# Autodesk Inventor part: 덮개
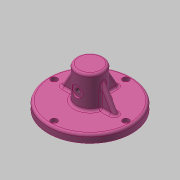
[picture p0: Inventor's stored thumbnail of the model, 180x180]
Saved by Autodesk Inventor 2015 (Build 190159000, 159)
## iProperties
Created: 2017-08
Part Number: 덮개
Material: 알루미늄 6061
Document SubType Name: Modeling
Designer: mduedu
Density: 2.71 g/cm^3
Mass: 336.252 g
Surface Area: 314.319 cm^2
Volume: 124.078 cm^3
Appearance: 분홍색
Author: mduedu
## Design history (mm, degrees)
sketch "스케치1"
  geometry: C1 r 52.5 at (0, 0); 1 further point
  constraints: 1 centre point, 1 coincident
  dimensions: "d55" = 105 diameter of C1
extrude "돌출1" new body sketch "스케치1" distance "d5" = 10; taper "d6" = 0 deg
sketch "스케치2"
  geometry: C1 r 17 at (0, 0); 1 further point
  constraints: 1 centre point, 1 coincident
  dimensions: "d74" = 34 diameter of C1
extrude "돌출2" join sketch "스케치2" distance "d9" = 40; taper "d10" = 0 deg
sketch "스케치3"
  geometry: C1 r 37 at (0, 0); 1 further point
  constraints: 1 centre point, 1 coincident
  dimensions: "d56" = 74 diameter of C1
extrude "돌출3" join sketch "스케치3" distance "d12" = 8; taper "d13" = 0 deg
sketch "스케치4"
  geometry: C1 r 33 at (0, 0); 1 further point
  constraints: 1 centre point, 1 coincident
  dimensions: "d57" = 66 diameter of C1
extrude "돌출4" cut sketch "스케치4" distance "d16" = 7; taper "d17" = 0 deg
sketch "스케치5"
  geometry: C1 r 9 at (0, 0); 1 further point
  constraints: 1 centre point, 1 coincident
  dimensions: "d18" = 18 diameter of C1
extrude "돌출5" cut sketch "스케치5" distance "d19" = 47; taper "d20" = 0 deg
node "작업 평면1"
sketch "스케치11"
  geometry: L1 (-52.5, -10)-(52.5, -10) reference; 2 further points
  constraints: 1 vertical alignment
  dimensions: "d78" = 28 distance from line of point (0, 18) L1
hole "구멍5" sketch "스케치11" at (0, 18) diameter "d79" = 5.917; stored, may be unused: countersink angle "d83" = 90 deg, drill point angle "d85" = 118 deg; dims "d80" = 6, "d81" = 14, "d82" = 2, "d84" = 8
fillet "모깎기9" dims "d86" = 3
fillet "모깎기5" dims "d40" = 1
sketch "스케치12"
  geometry: C1 r 2.5 at (0, 0); 1 further point
  constraints: 1 centre point, 1 coincident
  dimensions: "d87" = 5 diameter of C1
extrude "돌출6" join sketch "스케치12" distance "d88" = 3; taper "d89" = 0 deg
fillet "모깎기10" dims "d91" = 1
chamfer "모따기1" distance "d41" = 1; stored, may be unused: second distance "d42" = 2, angle "d43" = 45 deg
fillet "모깎기7" dims "d45" = 3
fillet "모깎기8" dims "d46" = 3
sketch "스케치10" dims "d59" = 90
  geometry: 3 further points
  constraints: 2 vertical alignment, 1 coincident, 2 other
hole "구멍4" sketch "스케치10" at (0, 45) diameter "d60" = 4.5; stored, may be unused: countersink angle "d64" = 90 deg, drill point angle "d66" = 118 deg; dims "d61" = 6, "d62" = 8, "d63" = 4.6, "d65" = 8
sketch "스케치13"
  geometry: L1 (52.5, 7)-(52.5, 0) reference; L2 (52.5, 0)-(47.25, 0) reference; L3 (47.25, 0)-(47.25, 5.4) reference; L4 (47.25, 5.4)-(49, 5.4) reference; L5 (49, 5.4)-(49, 10) reference; L6 (49, 10)-(49.5, 10) reference; L7 (-49.5, 10)-(-49, 10) reference; L8 (-49, 10)-(-49, 5.4) reference; L9 (-49, 5.4)-(-47.25, 5.4) reference; L10 (-47.25, 5.4)-(-47.25, 0) reference; L11 (-47.25, 0)-(-52.5, 0) reference; L12 (-52.5, 0)-(-52.5, 7) reference; L13 (-3.5, 46)-(-8, 46) reference; L14 (-9, 45)-(-9, -1) reference; L15 (-9, -1)-(-30, -1) reference; L16 (-33, -4)-(-33, -8) reference; L17 (-33, -8)-(-36, -8) reference; L18 (-36, -8)-(-37, -7) reference; L19 (-37, -7)-(-37, 0) reference; L20 (-37, 0)-(-42.75, 0) reference; L21 (-42.75, 0)-(-42.75, 5.4) reference; L22 (-42.75, 5.4)-(-41, 5.4) reference; L23 (-41, 5.4)-(-41, 10) reference; L24 (-41, 10)-(-20, 10) reference; L25 (-17, 13)-(-17, 47) reference; L26 (-14, 50)-(14, 50) reference; L27 (17, 47)-(17, 13) reference; L28 (20, 10)-(41, 10) reference; L29 (41, 10)-(41, 5.4) reference; L30 (41, 5.4)-(42.75, 5.4) reference; L31 (42.75, 5.4)-(42.75, 0) reference; L32 (42.75, 0)-(37, 0) reference; L33 (37, 0)-(37, -7) reference; L34 (37, -7)-(36, -8) reference; L35 (36, -8)-(33, -8) reference; L36 (33, -8)-(33, -4) reference; L37 (30, -1)-(9, -1) reference; L38 (9, -1)-(9, 45) reference; L39 (8, 46)-(3.5, 46) reference; L40 (2.5, 45)-(2.5, 43) reference; L41 (2.5, 43)-(-2.5, 43) reference; L42 (-2.5, 43)-(-2.5, 45) reference; L43 (17, 40)-(34.321, 10); L44 (-49.5, 10)-(49.5, 10) reference; A1 r 3 centre (49.5, 7) between (52.5, 7) and (49.5, 10) reference; A2 r 3 centre (-49.5, 7) between (-49.5, 10) and (-52.5, 7) reference; A3 r 1 centre (-3.5, 45) between (-2.5, 45) and (-3.5, 46) reference; A4 r 1 centre (-8, 45) between (-8, 46) and (-9, 45) reference; A5 r 3 centre (-30, -4) between (-30, -1) and (-33, -4) reference; A6 r 3 centre (-20, 13) between (-20, 10) and (-17, 13) reference; A7 r 3 centre (-14, 47) between (-14, 50) and (-17, 47) reference; A8 r 3 centre (14, 47) between (17, 47) and (14, 50) reference; A9 r 3 centre (20, 13) between (17, 13) and (20, 10) reference; A10 r 3 centre (30, -4) between (33, -4) and (30, -1) reference; A11 r 1 centre (8, 45) between (9, 45) and (8, 46) reference; A12 r 1 centre (3.5, 45) between (3.5, 46) and (2.5, 45) reference; 1 further point
  constraints: 2 end point, 2 point on line
  dimensions: "d98" = 120 deg angle of L43 L28; "d99" = 30 distance from line of L43.start L44
feature "리브1" sketch "스케치13" dims "d100" = 1, "d101" = 6, "d102" = 0, "d103" = 0, "d104" = 1, "d105" = 1
fillet "모깎기11" dims "d106" = 3
fillet "모깎기12" dims "d107" = 3
node "솔리드1"
pattern_circular "원형 패턴1" dims angle "d68" = 360 deg
pattern_circular "원형 패턴2" dims "d109" = 270 deg
node "절단 모서리 투영1"
